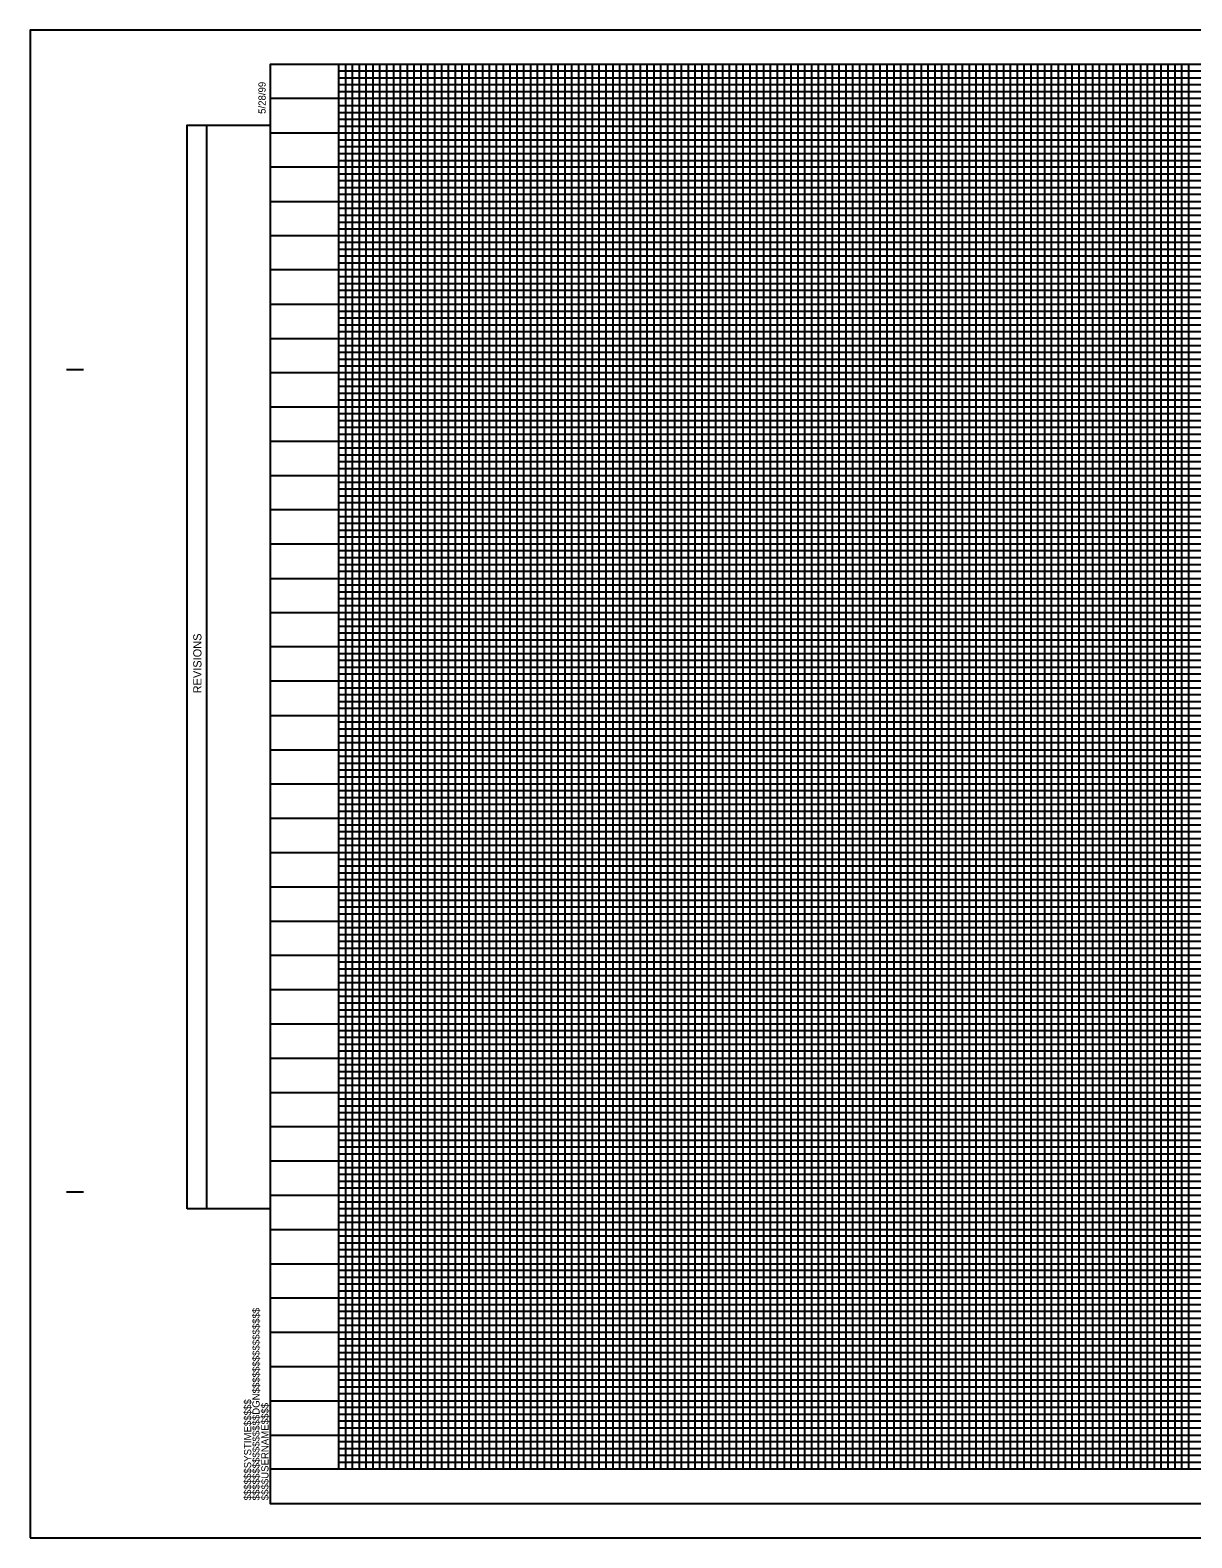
# Model space of a CAD drawing. Extents: x 1967100 to 1968800, y 964086 to 965186.
# Drawn here: x 1967100 to 1967947, y 964086 to 965186 of the extents above; entities that cross this region are included whole.
import ezdxf

# ---------------------------------------------------------------- set-up
doc = ezdxf.new("R2010")
doc.units = 0
for name, color, linetype in [('Sheet Block Revision CELL', 7, 'Continuous'), ('Sheet Block System Information CELL', 7, 'Continuous'), ('Sheet Plan And Profile CELL', 7, 'Continuous'), ('Sheet Profile CELL', 7, 'Continuous'), ('Sheet Profile Grid Major CELL', 7, 'Continuous'), ('Sheet Profile Grid Middle CELL', 7, 'Continuous'), ('Sheet Profile Grid Minor CELL', 7, 'Continuous'), ('Stewart Plot Border Xerox6279 and LJ5000', 7, 'Continuous')]:
    doc.layers.add(name, color=color, linetype=linetype)

msp = doc.modelspace()

# ---------------------------------------------------------------- linework, layer by layer
at = {"layer": 'Sheet Block Revision CELL'}
msp.add_line((1967228.5, 964326), (1967228.5, 965116.6), dxfattribs=at)
msp.add_lwpolyline([(1967214, 964326), (1967214, 965116.6), (1967274.5, 965116.6), (1967274.5, 964326)], close=True, dxfattribs=at)
at = {"layer": 'Sheet Block System Information CELL'}
msp.add_line((1967274.5, 964111), (1967274.5, 964111), dxfattribs=at)
at = {"layer": 'Sheet Plan And Profile CELL'}
for p, q in [((1967126, 964938.5), (1967138.5, 964938.5)), ((1967126, 964338.5), (1967138.5, 964338.5)), ((1967274.5, 964111), (1967274.5, 964111)), ((1967274.5, 964111), (1967274.5, 964111)), ((1967274.5, 964111), (1967274.5, 964111)), ((1967274.5, 964111), (1967274.5, 964111)), ((1967274.5, 964111), (1967274.5, 964111))]:
    msp.add_line(p, q, dxfattribs=at)
msp.add_lwpolyline([(1968774.5, 965161), (1967274.5, 965161), (1967274.5, 964111), (1968774.5, 964111)], close=True, dxfattribs=at)
at = {"layer": 'Sheet Profile CELL'}
msp.add_line((1968774.5, 964136), (1967274.5, 964136), dxfattribs=at)
at = {"layer": 'Sheet Profile Grid Major CELL'}
for p, q in [((1967324.5, 965161), (1967324.5, 964136)), ((1967374.5, 965161), (1967374.5, 964136)), ((1967424.5, 965161), (1967424.5, 964136)), ((1967474.5, 965161), (1967474.5, 964136)), ((1967524.5, 965161), (1967524.5, 964136)), ((1967574.5, 965161), (1967574.5, 964136)), ((1967624.5, 965161), (1967624.5, 964136)), ((1967674.5, 965161), (1967674.5, 964136)), ((1967724.5, 965161), (1967724.5, 964136)), ((1967774.5, 965161), (1967774.5, 964136)), ((1967824.5, 965161), (1967824.5, 964136)), ((1967874.5, 965161), (1967874.5, 964136)), ((1967924.5, 965161), (1967924.5, 964136)), ((1968574.5, 965136), (1967274.5, 965136)), ((1968574.5, 965086), (1967274.5, 965086)), ((1968574.5, 965036), (1967274.5, 965036)), ((1967274.5, 964986), (1968574.5, 964986)), ((1968774.5, 964936), (1967274.5, 964936)), ((1967274.5, 964886), (1968774.5, 964886)), ((1968774.5, 964836), (1967274.5, 964836)), ((1967274.5, 964786), (1968774.5, 964786)), ((1968774.5, 964736), (1967274.5, 964736)), ((1967274.5, 964686), (1968774.5, 964686)), ((1967274.5, 964636), (1968774.5, 964636)), ((1967274.5, 964586), (1968774.5, 964586)), ((1967274.5, 964536), (1968774.5, 964536)), ((1967274.5, 964486), (1968774.5, 964486)), ((1967274.5, 964436), (1968774.5, 964436)), ((1967274.5, 964386), (1968774.5, 964386)), ((1967274.5, 964336), (1968774.5, 964336)), ((1967274.5, 964286), (1968774.5, 964286)), ((1967274.5, 964236), (1968774.5, 964236)), ((1967274.5, 964186), (1968774.5, 964186))]:
    msp.add_line(p, q, dxfattribs=at)
at = {"layer": 'Sheet Profile Grid Middle CELL'}
for p, q in [((1967349.5, 965161), (1967349.5, 964136)), ((1967399.5, 965161), (1967399.5, 964136)), ((1967449.5, 965161), (1967449.5, 964136)), ((1967499.5, 965161), (1967499.5, 964136)), ((1967549.5, 965161), (1967549.5, 964136)), ((1967599.5, 965161), (1967599.5, 964136)), ((1967649.5, 965161), (1967649.5, 964136)), ((1967699.5, 965161), (1967699.5, 964136)), ((1967749.5, 965161), (1967749.5, 964136)), ((1967799.5, 965161), (1967799.5, 964136)), ((1967849.5, 965161), (1967849.5, 964136)), ((1967899.5, 965161), (1967899.5, 964136)), ((1967274.5, 965111), (1968574.5, 965111)), ((1967274.5, 965061), (1968574.5, 965061)), ((1968574.5, 965011), (1967274.5, 965011)), ((1967274.5, 964961), (1968574.5, 964961)), ((1968774.5, 964911), (1967274.5, 964911)), ((1967274.5, 964861), (1968774.5, 964861)), ((1968774.5, 964811), (1967274.5, 964811)), ((1967274.5, 964761), (1968774.5, 964761)), ((1968774.5, 964711), (1967274.5, 964711)), ((1967274.5, 964661), (1968774.5, 964661)), ((1967274.5, 964611), (1968774.5, 964611)), ((1967274.5, 964561), (1968774.5, 964561)), ((1967274.5, 964511), (1968774.5, 964511)), ((1967274.5, 964461), (1968774.5, 964461)), ((1967274.5, 964411), (1968774.5, 964411)), ((1967274.5, 964361), (1968774.5, 964361)), ((1967274.5, 964311), (1968774.5, 964311)), ((1967274.5, 964261), (1968774.5, 964261)), ((1967274.5, 964211), (1968774.5, 964211)), ((1967274.5, 964161), (1968774.5, 964161))]:
    msp.add_line(p, q, dxfattribs=at)
at = {"layer": 'Sheet Profile Grid Minor CELL'}
for p, q in [((1968574.5, 965156), (1967324.5, 965156)), ((1967329.5, 965161), (1967329.5, 964136)), ((1967334.5, 965161), (1967334.5, 964136)), ((1967339.5, 965161), (1967339.5, 964136)), ((1967344.5, 965161), (1967344.5, 964136)), ((1967354.5, 965161), (1967354.5, 964136)), ((1967359.5, 965161), (1967359.5, 964136)), ((1967364.5, 965161), (1967364.5, 964136)), ((1967369.5, 965161), (1967369.5, 964136)), ((1967379.5, 965161), (1967379.5, 964136)), ((1967384.5, 965161), (1967384.5, 964136)), ((1967389.5, 965161), (1967389.5, 964136)), ((1967394.5, 965161), (1967394.5, 964136)), ((1967404.5, 965161), (1967404.5, 964136)), ((1967409.5, 965161), (1967409.5, 964136)), ((1967414.5, 965161), (1967414.5, 964136)), ((1967419.5, 965161), (1967419.5, 964136)), ((1967429.5, 965161), (1967429.5, 964136)), ((1967434.5, 965161), (1967434.5, 964136)), ((1967439.5, 965161), (1967439.5, 964136)), ((1967444.5, 965161), (1967444.5, 964136)), ((1967454.5, 965161), (1967454.5, 964136)), ((1967459.5, 965161), (1967459.5, 964136)), ((1967464.5, 965161), (1967464.5, 964136)), ((1967469.5, 965161), (1967469.5, 964136)), ((1967479.5, 965161), (1967479.5, 964136)), ((1967484.5, 965161), (1967484.5, 964136)), ((1967489.5, 965161), (1967489.5, 964136)), ((1967494.5, 965161), (1967494.5, 964136)), ((1967504.5, 965161), (1967504.5, 964136)), ((1967509.5, 965161), (1967509.5, 964136)), ((1967514.5, 965161), (1967514.5, 964136)), ((1967519.5, 965161), (1967519.5, 964136)), ((1967529.5, 965161), (1967529.5, 964136)), ((1967534.5, 965161), (1967534.5, 964136)), ((1967539.5, 965161), (1967539.5, 964136)), ((1967544.5, 965161), (1967544.5, 964136)), ((1967554.5, 965161), (1967554.5, 964136)), ((1967559.5, 965161), (1967559.5, 964136)), ((1967564.5, 965161), (1967564.5, 964136)), ((1967569.5, 965161), (1967569.5, 964136)), ((1967579.5, 965161), (1967579.5, 964136)), ((1967584.5, 965161), (1967584.5, 964136)), ((1967589.5, 965161), (1967589.5, 964136)), ((1967594.5, 965161), (1967594.5, 964136)), ((1967604.5, 965161), (1967604.5, 964136)), ((1967609.5, 965161), (1967609.5, 964136)), ((1967614.5, 965161), (1967614.5, 964136)), ((1967619.5, 965161), (1967619.5, 964136)), ((1967629.5, 965161), (1967629.5, 964136)), ((1967634.5, 965161), (1967634.5, 964136)), ((1967639.5, 965161), (1967639.5, 964136)), ((1967644.5, 965161), (1967644.5, 964136)), ((1967654.5, 965161), (1967654.5, 964136)), ((1967659.5, 965161), (1967659.5, 964136)), ((1967664.5, 965161), (1967664.5, 964136)), ((1967669.5, 965161), (1967669.5, 964136)), ((1967679.5, 965161), (1967679.5, 964136)), ((1967684.5, 965161), (1967684.5, 964136)), ((1967689.5, 965161), (1967689.5, 964136)), ((1967694.5, 965161), (1967694.5, 964136)), ((1967704.5, 965161), (1967704.5, 964136)), ((1967709.5, 965161), (1967709.5, 964136)), ((1967714.5, 965161), (1967714.5, 964136)), ((1967719.5, 965161), (1967719.5, 964136)), ((1967729.5, 965161), (1967729.5, 964136)), ((1967734.5, 965161), (1967734.5, 964136)), ((1967739.5, 965161), (1967739.5, 964136)), ((1967744.5, 965161), (1967744.5, 964136)), ((1967754.5, 965161), (1967754.5, 964136)), ((1967759.5, 965161), (1967759.5, 964136)), ((1967764.5, 965161), (1967764.5, 964136)), ((1967769.5, 965161), (1967769.5, 964136)), ((1967779.5, 965161), (1967779.5, 964136)), ((1967784.5, 965161), (1967784.5, 964136)), ((1967789.5, 965161), (1967789.5, 964136)), ((1967794.5, 965161), (1967794.5, 964136)), ((1967804.5, 965161), (1967804.5, 964136)), ((1967809.5, 965161), (1967809.5, 964136)), ((1967814.5, 965161), (1967814.5, 964136)), ((1967819.5, 965161), (1967819.5, 964136)), ((1967829.5, 965161), (1967829.5, 964136)), ((1967834.5, 965161), (1967834.5, 964136)), ((1967839.5, 965161), (1967839.5, 964136)), ((1967844.5, 965161), (1967844.5, 964136)), ((1967854.5, 965161), (1967854.5, 964136)), ((1967859.5, 965161), (1967859.5, 964136)), ((1967864.5, 965161), (1967864.5, 964136)), ((1967869.5, 965161), (1967869.5, 964136)), ((1967879.5, 965161), (1967879.5, 964136)), ((1967884.5, 965161), (1967884.5, 964136)), ((1967889.5, 965161), (1967889.5, 964136)), ((1967894.5, 965161), (1967894.5, 964136)), ((1967904.5, 965161), (1967904.5, 964136)), ((1967909.5, 965161), (1967909.5, 964136)), ((1967914.5, 965161), (1967914.5, 964136)), ((1967919.5, 965161), (1967919.5, 964136)), ((1967929.5, 965161), (1967929.5, 964136)), ((1967934.5, 965161), (1967934.5, 964136)), ((1967939.5, 965161), (1967939.5, 964136)), ((1967944.5, 965161), (1967944.5, 964136)), ((1968574.5, 965151), (1967324.5, 965151)), ((1968574.5, 965146), (1967324.5, 965146)), ((1968574.5, 965141), (1967324.5, 965141)), ((1967324.5, 965131), (1968574.5, 965131)), ((1967324.5, 965126), (1968574.5, 965126)), ((1967324.5, 965121), (1968574.5, 965121)), ((1967324.5, 965116), (1968574.5, 965116)), ((1967324.5, 965106), (1968574.5, 965106)), ((1967324.5, 965101), (1968574.5, 965101)), ((1967324.5, 965096), (1968574.5, 965096)), ((1967324.5, 965091), (1968574.5, 965091)), ((1968574.5, 965081), (1967324.5, 965081)), ((1968574.5, 965076), (1967324.5, 965076)), ((1968574.5, 965071), (1967324.5, 965071)), ((1968574.5, 965066), (1967324.5, 965066)), ((1967324.5, 965056), (1968574.5, 965056)), ((1967324.5, 965051), (1968574.5, 965051)), ((1967324.5, 965046), (1968574.5, 965046)), ((1967324.5, 965041), (1968574.5, 965041)), ((1968574.5, 965031), (1967324.5, 965031)), ((1968574.5, 965026), (1967324.5, 965026)), ((1968574.5, 965021), (1967324.5, 965021)), ((1968574.5, 965016), (1967324.5, 965016)), ((1968574.5, 965006), (1967324.5, 965006)), ((1968574.5, 965001), (1967324.5, 965001)), ((1968574.5, 964996), (1967324.5, 964996)), ((1968574.5, 964991), (1967324.5, 964991)), ((1967324.5, 964981), (1968574.5, 964981)), ((1967324.5, 964976), (1968574.5, 964976)), ((1967324.5, 964971), (1968574.5, 964971)), ((1967324.5, 964966), (1968574.5, 964966)), ((1967324.5, 964956), (1968724.5, 964956)), ((1967324.5, 964951), (1968724.5, 964951)), ((1967324.5, 964946), (1968724.5, 964946)), ((1967324.5, 964941), (1968724.5, 964941)), ((1968724.5, 964931), (1967324.5, 964931)), ((1968724.5, 964926), (1967324.5, 964926)), ((1968724.5, 964921), (1967324.5, 964921)), ((1968724.5, 964916), (1967324.5, 964916)), ((1968724.5, 964906), (1967324.5, 964906)), ((1968724.5, 964901), (1967324.5, 964901)), ((1968724.5, 964896), (1967324.5, 964896)), ((1968724.5, 964891), (1967324.5, 964891)), ((1968724.5, 964881), (1967324.5, 964881)), ((1968724.5, 964876), (1967324.5, 964876)), ((1968724.5, 964871), (1967324.5, 964871)), ((1968724.5, 964866), (1967324.5, 964866)), ((1968724.5, 964856), (1967324.5, 964856)), ((1968724.5, 964851), (1967324.5, 964851)), ((1968724.5, 964846), (1967324.5, 964846)), ((1968724.5, 964841), (1967324.5, 964841)), ((1968724.5, 964831), (1967324.5, 964831)), ((1968724.5, 964826), (1967324.5, 964826)), ((1968724.5, 964821), (1967324.5, 964821)), ((1968724.5, 964816), (1967324.5, 964816)), ((1968724.5, 964806), (1967324.5, 964806)), ((1968724.5, 964801), (1967324.5, 964801)), ((1968724.5, 964796), (1967324.5, 964796)), ((1968724.5, 964791), (1967324.5, 964791)), ((1968724.5, 964781), (1967324.5, 964781)), ((1968724.5, 964776), (1967324.5, 964776)), ((1968724.5, 964771), (1967324.5, 964771)), ((1968724.5, 964766), (1967324.5, 964766)), ((1968724.5, 964756), (1967324.5, 964756)), ((1968724.5, 964751), (1967324.5, 964751)), ((1968724.5, 964746), (1967324.5, 964746)), ((1968724.5, 964741), (1967324.5, 964741)), ((1968724.5, 964731), (1967324.5, 964731)), ((1968724.5, 964726), (1967324.5, 964726)), ((1968724.5, 964721), (1967324.5, 964721)), ((1968724.5, 964716), (1967324.5, 964716)), ((1968724.5, 964706), (1967324.5, 964706)), ((1968724.5, 964701), (1967324.5, 964701)), ((1968724.5, 964696), (1967324.5, 964696)), ((1968724.5, 964691), (1967324.5, 964691)), ((1968724.5, 964681), (1967324.5, 964681)), ((1968724.5, 964676), (1967324.5, 964676)), ((1968724.5, 964671), (1967324.5, 964671)), ((1968724.5, 964666), (1967324.5, 964666)), ((1968724.5, 964656), (1967324.5, 964656)), ((1968724.5, 964651), (1967324.5, 964651)), ((1968724.5, 964646), (1967324.5, 964646)), ((1968724.5, 964641), (1967324.5, 964641)), ((1968724.5, 964631), (1967324.5, 964631)), ((1968724.5, 964626), (1967324.5, 964626)), ((1968724.5, 964621), (1967324.5, 964621)), ((1968724.5, 964616), (1967324.5, 964616)), ((1968724.5, 964606), (1967324.5, 964606)), ((1968724.5, 964601), (1967324.5, 964601)), ((1968724.5, 964596), (1967324.5, 964596)), ((1968724.5, 964591), (1967324.5, 964591)), ((1968724.5, 964581), (1967324.5, 964581)), ((1968724.5, 964576), (1967324.5, 964576)), ((1968724.5, 964571), (1967324.5, 964571)), ((1968724.5, 964566), (1967324.5, 964566)), ((1968724.5, 964556), (1967324.5, 964556)), ((1968724.5, 964551), (1967324.5, 964551)), ((1968724.5, 964546), (1967324.5, 964546)), ((1968724.5, 964541), (1967324.5, 964541)), ((1968724.5, 964531), (1967324.5, 964531)), ((1968724.5, 964526), (1967324.5, 964526)), ((1968724.5, 964521), (1967324.5, 964521)), ((1968724.5, 964516), (1967324.5, 964516)), ((1968724.5, 964506), (1967324.5, 964506)), ((1968724.5, 964501), (1967324.5, 964501)), ((1968724.5, 964496), (1967324.5, 964496)), ((1968724.5, 964491), (1967324.5, 964491)), ((1968724.5, 964481), (1967324.5, 964481)), ((1968724.5, 964476), (1967324.5, 964476)), ((1968724.5, 964471), (1967324.5, 964471)), ((1968724.5, 964466), (1967324.5, 964466)), ((1968724.5, 964456), (1967324.5, 964456)), ((1968724.5, 964451), (1967324.5, 964451)), ((1968724.5, 964446), (1967324.5, 964446)), ((1968724.5, 964441), (1967324.5, 964441)), ((1968724.5, 964431), (1967324.5, 964431)), ((1968724.5, 964426), (1967324.5, 964426)), ((1968724.5, 964421), (1967324.5, 964421)), ((1968724.5, 964416), (1967324.5, 964416)), ((1968724.5, 964406), (1967324.5, 964406)), ((1968724.5, 964401), (1967324.5, 964401)), ((1968724.5, 964396), (1967324.5, 964396)), ((1968724.5, 964391), (1967324.5, 964391)), ((1968724.5, 964381), (1967324.5, 964381)), ((1968724.5, 964376), (1967324.5, 964376)), ((1968724.5, 964371), (1967324.5, 964371)), ((1968724.5, 964366), (1967324.5, 964366)), ((1968724.5, 964356), (1967324.5, 964356)), ((1968724.5, 964351), (1967324.5, 964351)), ((1968724.5, 964346), (1967324.5, 964346)), ((1968724.5, 964341), (1967324.5, 964341)), ((1968724.5, 964331), (1967324.5, 964331)), ((1968724.5, 964326), (1967324.5, 964326)), ((1968724.5, 964321), (1967324.5, 964321)), ((1968724.5, 964316), (1967324.5, 964316)), ((1968724.5, 964306), (1967324.5, 964306)), ((1968724.5, 964301), (1967324.5, 964301)), ((1968724.5, 964296), (1967324.5, 964296)), ((1968724.5, 964291), (1967324.5, 964291)), ((1968724.5, 964281), (1967324.5, 964281)), ((1968724.5, 964276), (1967324.5, 964276)), ((1968724.5, 964271), (1967324.5, 964271)), ((1968724.5, 964266), (1967324.5, 964266)), ((1968724.5, 964256), (1967324.5, 964256)), ((1968724.5, 964251), (1967324.5, 964251)), ((1968724.5, 964246), (1967324.5, 964246)), ((1968724.5, 964241), (1967324.5, 964241)), ((1968724.5, 964231), (1967324.5, 964231)), ((1968724.5, 964226), (1967324.5, 964226)), ((1968724.5, 964221), (1967324.5, 964221)), ((1968724.5, 964216), (1967324.5, 964216)), ((1968724.5, 964206), (1967324.5, 964206)), ((1968724.5, 964201), (1967324.5, 964201)), ((1968724.5, 964196), (1967324.5, 964196)), ((1968724.5, 964191), (1967324.5, 964191)), ((1968724.5, 964181), (1967324.5, 964181)), ((1968724.5, 964176), (1967324.5, 964176)), ((1968724.5, 964171), (1967324.5, 964171)), ((1968724.5, 964166), (1967324.5, 964166)), ((1968724.5, 964156), (1967324.5, 964156)), ((1968724.5, 964151), (1967324.5, 964151)), ((1968724.5, 964146), (1967324.5, 964146)), ((1968724.5, 964141), (1967324.5, 964141))]:
    msp.add_line(p, q, dxfattribs=at)
at = {"layer": 'Stewart Plot Border Xerox6279 and LJ5000'}
msp.add_lwpolyline([(1967099.5, 964086), (1968799.5, 964086), (1968799.5, 965186), (1967099.5, 965186)], close=True, dxfattribs=at)

# ---------------------------------------------------------------- texts
at = {"layer": 'Sheet Block Revision CELL'}
msp.add_text('REVISIONS', height=6, rotation=90, dxfattribs=at).set_placement((1967224.5, 964702.1))
at = {"layer": 'Sheet Block System Information CELL'}
for s, p in [('$$$$$$$$$$$$$$$$DGN$$$$$$$$$$$$$$$$', (1967266.9, 964113.3)), ('$$$$$$SYSTIME$$$$$', (1967260.8, 964113.3)), ('$$$$USERNAME$$$$', (1967273.4, 964113.4))]:
    msp.add_text(s, height=5.25, rotation=90, dxfattribs=at).set_placement(p)
at = {"layer": 'Sheet Plan And Profile CELL'}
msp.add_text('5/28/99', height=5.25, rotation=90, dxfattribs=at).set_placement((1967271.3, 965124.9))

doc.saveas('drawing.dxf')
